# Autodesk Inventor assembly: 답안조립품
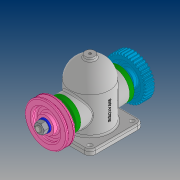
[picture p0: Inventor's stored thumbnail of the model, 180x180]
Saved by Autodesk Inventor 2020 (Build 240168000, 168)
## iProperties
Created: 2021-08
Part Number: 답안조립품
Document SubType Name: Assembly
Designer: PC312-
Author: PC312-
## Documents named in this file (14)
- C:\Users\PC312-\Desktop\710809V1006\답안조립품.iam
- C:\Users\PC312-\Desktop\710809V1006\본체.ipt
- C:\Users\PC312-\Desktop\710809V1006\축.ipt
- C:\Users\PC312-\Desktop\710809V1006\베어링 6203.ipt
- C:\Users\PC312-\Desktop\710809V1006\부시.ipt
- C:\Users\PC312-\Desktop\710809V1006\커버.ipt
- C:\Users\PC312-\Desktop\710809V1006\오일 실 26 38 8.ipt
- C:\Users\PC312-\Desktop\710809V1006\스퍼기어.ipt
- C:\Users\PC312-\Desktop\710809V1006\V-벨트풀리.ipt
- V-벨트풀리.ipt
- C:\Users\PC312-\Desktop\710809V1006\키 5x5x12.ipt
- C:\Users\PC312-\Desktop\710809V1006\와셔 12x24.ipt
- C:\Users\PC312-\Desktop\710809V1006\너트 M12x1.25.ipt
- C:\Users\PC312-\Desktop\710809V1006\볼트 M4.ipt
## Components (1 placed, 1 different names)
1. V-벨트풀리:1
